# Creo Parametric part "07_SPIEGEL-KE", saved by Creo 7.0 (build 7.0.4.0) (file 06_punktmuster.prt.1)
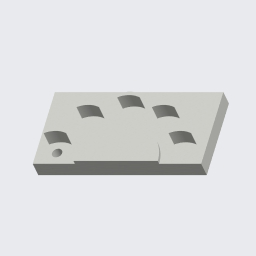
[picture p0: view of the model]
Units: millimeter Kilogram Sec (mmKs); MM, KILOGRAM, SECS
Materials in the file: S235JRG2

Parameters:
  PTC_MATERIAL_NAME = "S235JRG2"
  BENENNUNG = "XXX"
  DATUM = "XX.XX.XX"
  ERSTELLER = "ARINDA"
  TEILETYP = "Fertigungsteil"
  SELECT_EN_NAME = "S235JRG2"
  SELECT_DIN_NAME = "RSt37-2"
  SELECT_DIN_NUMBER = "1.0038"
  SELECT_ASTM_NAME = "A 283 M Grade 2"
  MATERIAL_GROUP = "ME_ST_Baustahl"
  STANDARD_EN_DELIVERYSPEC = "DIN EN 10025"
  STANDARD_DIN_DELIVERYSPEC = "DIN 17100"

Other parameters: MASSE

Created from: ARINDA-STARTTEIL.PRT

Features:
  1. coordinate system "CS0"
  2. datum plane "DTM1", "T_RECHTS_Y-Z"
  3. datum plane "DTM2", "T_OBEN_X-Z"
  4. datum plane "DTM3", "T_VORNE_X-Y"
  5. datum axis "T_X-ACHSE"
  6. datum axis "A_1"
  7. datum axis "A_2"
  8. extrusion "Profil 1"
  9. extrusion "Profil 3"
  10. sketch "Skizze 1"
  11. pattern "Muster 1"
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
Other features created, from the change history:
  extrusion "Profil 2"
  extrusion "Profil 2 [22]"
  extrusion "Profil 2 [23]"
  extrusion "Profil 2 [25]"
  extrusion "Profil 2 [26]"
  hole "Bohrung 1" (2 times)
  pattern "Muster 2" (4 times)
  hole "Bohrung 1 [21]" (2 times)
  hole "Bohrung 1 [22]" (4 times)
  hole "Bohrung 1 [23]" (4 times)
  hole "Bohrung 1 [25]" (4 times)
  hole "Bohrung 1 [26]" (4 times)
  extrusion "Profil 3" (5 times)
  extrusion "Profil 4"
  mirror "Spiegeln 1" (4 times)
  extrusion "Profil 3 (2)"
  pattern "Muster 1 (2)" (3 times)
  extrusion "Profil 2 (2) [1]" (3 times)
  extrusion "Profil 2 (2) [22]" (3 times)
  extrusion "Profil 2 (2) [23]" (3 times)
  extrusion "Profil 2 (2) [25]" (3 times)
  extrusion "Profil 2 (2) [26]" (3 times)

Other named items: T_BASIC, GRUNDPLATTE, MUSTER, STEG, HALBKREIS, T_Y-ACHSE, T_Z-ACHSE

Layers: 00_STD-ACHSEN, 00_STD-EBENEN, 00_STD-KOORDSYS, 01_ACHSEN, 01_KURVEN, KURVENELEMENTE, VOLUMENGEOMETRIE

Surfaces: 12 plane, 12 cylinder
